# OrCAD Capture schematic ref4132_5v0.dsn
size A; title: REF4132 5.0V; rev: 1.0; note: SNAS794
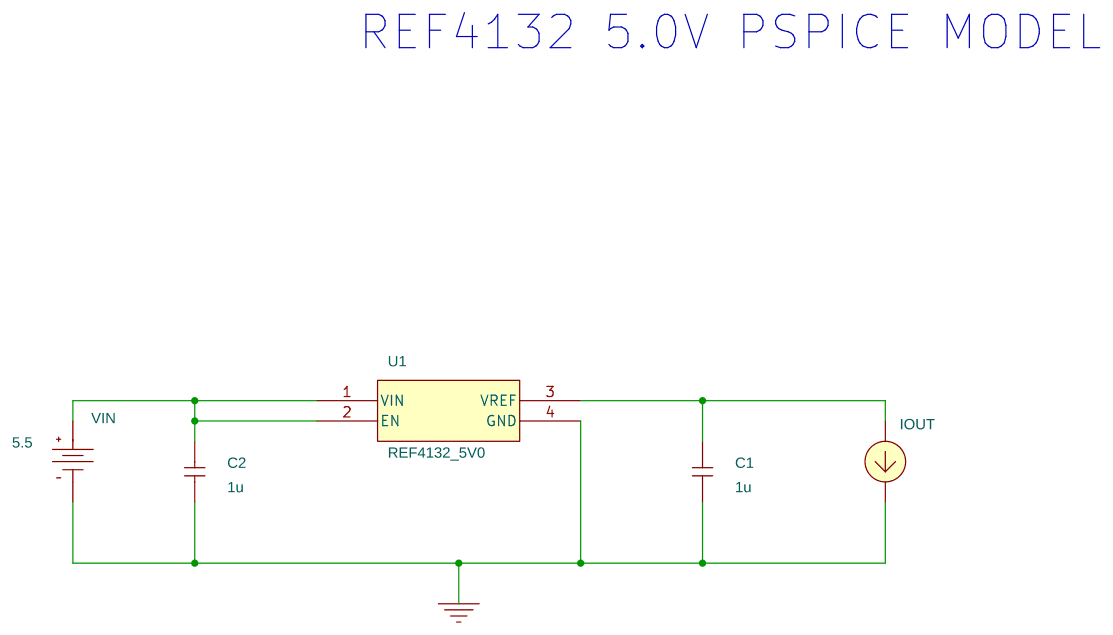
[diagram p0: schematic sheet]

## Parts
C1  1u  [cap196]
C2  1u  [cap196]
IOUT  IDC
U1  REF4132_5V0
VIN  VDC

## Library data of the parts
C1 C2 = C
IOUT = IDC
U1 = REF4132_5V0
VIN = VDC: DC: 5.5

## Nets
0: C1.1 C2.1 IOUT.2(-) U1.4(GND) VIN.1(-)
N00189: C2.2 U1.1(VIN) U1.2(EN) VIN.0(+)
N00276: C1.2 IOUT.1(+) U1.3(VREF)

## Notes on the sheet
- REF4132 5.0V PSPICE MODEL
